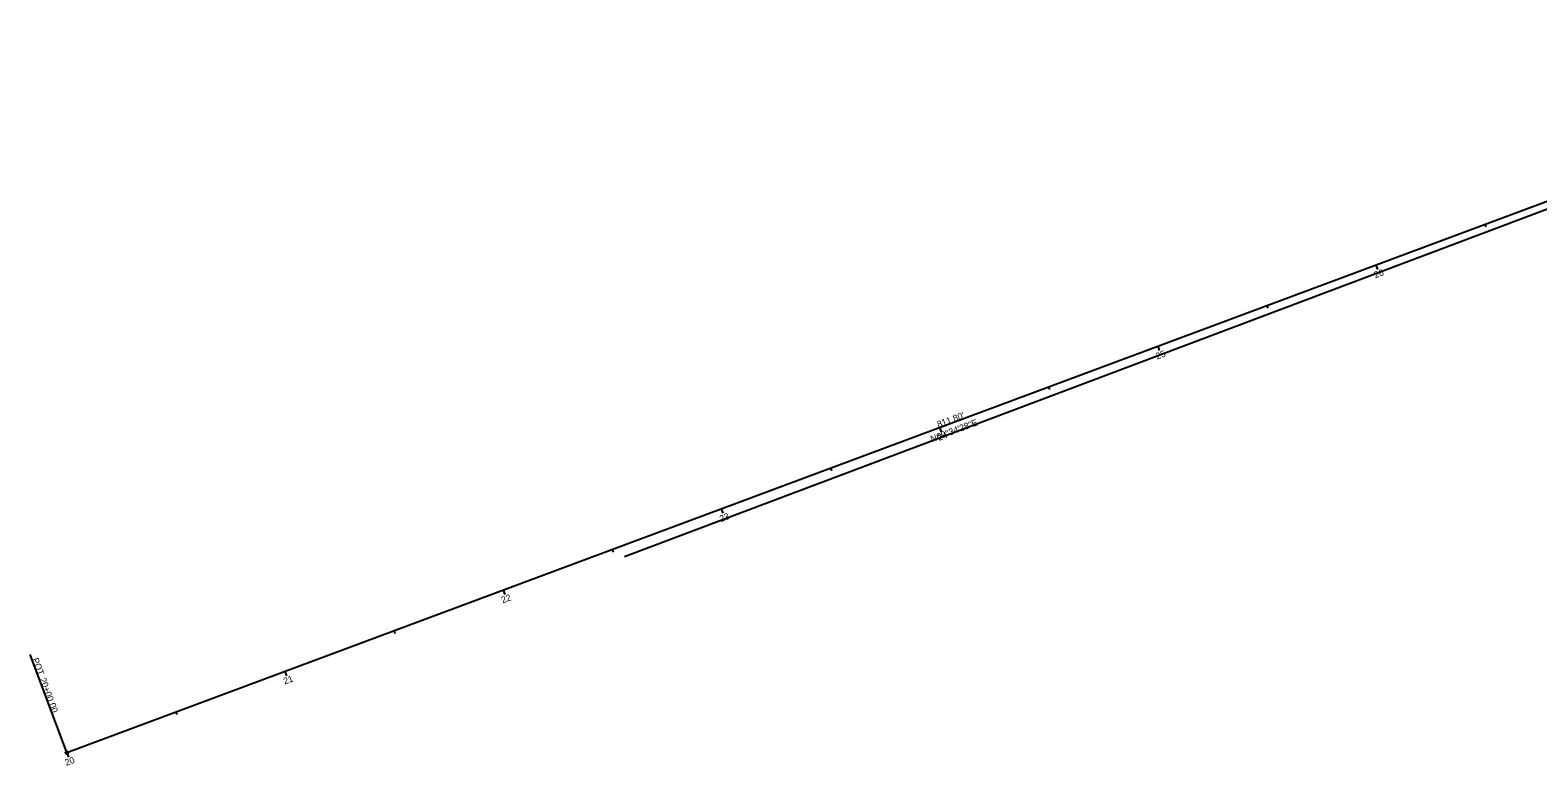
# Model space of a CAD drawing. Extents: x 2047945 to 2050534, y 355635 to 356996.
# Drawn here: x 2047945 to 2048592, y 355635 to 355950 of the extents above; entities that cross this region are included whole.
import ezdxf

# ---------------------------------------------------------------- set-up
doc = ezdxf.new("R2010")
doc.units = 0
for name, color, linetype in [('GE_X_Alignment_100_Bearings', 7, 'Continuous'), ('GE_X_Alignment_100_Cardinal_Points', 7, 'Continuous'), ('GE_X_Alignment_100_Distances', 7, 'Continuous'), ('GE_X_Alignment_100_Stations', 7, 'Continuous'), ('RW_X_CL', 7, 'Continuous'), ('SC_Scratch1', 7, 'Continuous')]:
    doc.layers.add(name, color=color, linetype=linetype)

msp = doc.modelspace()

# ---------------------------------------------------------------- linework, layer by layer
at = {"layer": 'GE_X_Alignment_100_Cardinal_Points'}
msp.add_line((2047960.38, 355640.2), (2047944.67, 355682.38), dxfattribs=at)
msp.add_circle((2047960.38, 355640.2), 0.6, dxfattribs=at)
at = {"layer": 'GE_X_Alignment_100_Stations'}
for p, q in [((2048569.51, 355867.05), (2048569.93, 355865.92)), ((2048522.65, 355849.6), (2048523.35, 355847.73)), ((2048475.8, 355832.15), (2048476.22, 355831.03)), ((2048428.94, 355814.7), (2048429.64, 355812.83)), ((2048382.09, 355797.25), (2048382.5, 355796.13)), ((2048335.23, 355779.8), (2048335.93, 355777.93)), ((2048288.37, 355762.35), (2048288.79, 355761.23)), ((2048241.52, 355744.9), (2048242.21, 355743.03)), ((2048194.66, 355727.45), (2048195.08, 355726.33)), ((2048147.8, 355710), (2048148.5, 355708.13)), ((2048100.95, 355692.55), (2048101.37, 355691.43)), ((2048054.09, 355675.1), (2048054.79, 355673.23)), ((2048007.23, 355657.65), (2048007.65, 355656.53)), ((2047960.38, 355640.2), (2047961.08, 355638.33))]:
    msp.add_line(p, q, dxfattribs=at)
at = {"layer": 'RW_X_CL'}
msp.add_line((2047960.38, 355640.2), (2048721.14, 355923.52), dxfattribs=at)
at = {"layer": 'SC_Scratch1'}
msp.add_line((2048200, 355724.36), (2048800, 355950.44), dxfattribs=at)

# ---------------------------------------------------------------- texts
at = {"layer": 'GE_X_Alignment_100_Bearings'}
msp.add_text('N69°34\'28"E', height=2.8, rotation=20.42564, dxfattribs=at).set_placement((2048331.96, 355773.46))
at = {"layer": 'GE_X_Alignment_100_Cardinal_Points'}
for s, p in [('POT', (2047945.49, 355680.32)), ('20+00.00', (2047948.67, 355671.77))]:
    msp.add_text(s, height=2.8, rotation=290.42564, dxfattribs=at).set_placement(p)
at = {"layer": 'GE_X_Alignment_100_Distances'}
msp.add_text("811.80'", height=2.8, rotation=20.42564, dxfattribs=at).set_placement((2048334.8, 355779.69))
at = {"layer": 'GE_X_Alignment_100_Stations'}
for s, p in [('26', (2048522.44, 355843.87)), ('25', (2048428.72, 355808.96)), ('24', (2048335.06, 355774.08)), ('23', (2048241.33, 355739.18)), ('22', (2048147.6, 355704.27)), ('21', (2048054.04, 355669.43)), ('20', (2047960.17, 355634.47))]:
    msp.add_text(s, height=2.8, rotation=20.42564, dxfattribs=at).set_placement(p)

doc.saveas('drawing.dxf')
